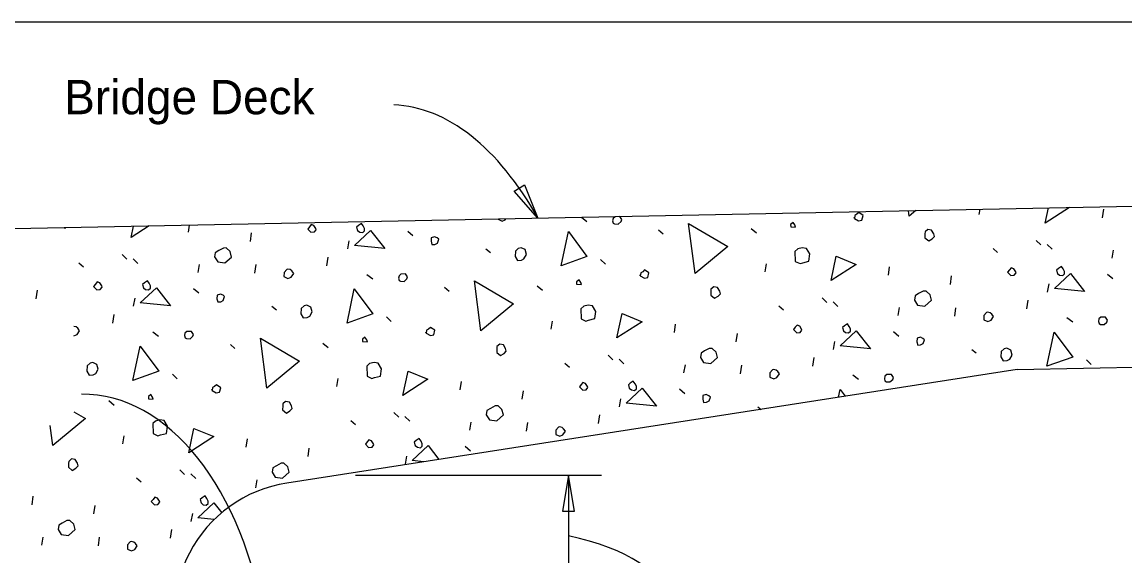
# Model space of a CAD drawing. Extents: x 112544 to 112597.1, y 111084 to 111107.1.
# Drawn here: x 112547.426 to 112552.277, y 111103.015 to 111105.363 of the extents above; entities that cross this region are included whole.
import ezdxf

# ---------------------------------------------------------------- set-up
doc = ezdxf.new("R2010")
doc.units = 0
for name, color, linetype in [('ActivePts-ConstElements', 7, 'Continuous'), ('Dimension', 7, 'Continuous'), ('Miscellaneous', 7, 'Continuous'), ('SupstrConc', 7, 'Continuous'), ('TextStructures', 7, 'Continuous')]:
    doc.layers.add(name, color=color, linetype=linetype)

msp = doc.modelspace()

# ---------------------------------------------------------------- linework, layer by layer
at = {"layer": 'ActivePts-ConstElements'}
msp.add_lwpolyline([(112543.9918, 111085.9039), (112574.7797, 111085.9039), (112574.7797, 111105.3634), (112543.9918, 111105.3634)], close=True, dxfattribs=at)
at = {"layer": 'Dimension'}
for p, q in [((112549.9754, 111103.3685), (112548.8921, 111103.3685)), ((112549.8296, 111103.3685), (112549.8296, 111102.8366))]:
    msp.add_line(p, q, dxfattribs=at)
for points in [[(112549.6951, 111104.5007), (112549.5904, 111104.6196), (112549.6355, 111104.6474)], [(112549.8296, 111103.3684), (112549.8031, 111103.2122), (112549.856, 111103.2122)]]:
    msp.add_lwpolyline(points, close=True, dxfattribs=at)
for centre, major_axis, ratio, start_param, end_param in [((112548.95, 111102.6319), (-0.1111, -2.3674), 0.464296, 2.502126, 3.141581), ((112547.7047, 111102.4058), (0.0174, -1.3204), 0.616683, 1.795781, 3.141615), ((112549.4704, 111102.8192), (-0.7827, 0), 0.407451, 3.141527, 4.235533)]:
    msp.add_ellipse(centre, major_axis=major_axis, ratio=ratio, start_param=start_param, end_param=end_param, dxfattribs=at)
at = {"layer": 'Miscellaneous'}
for p, q in [((112551.6363, 111104.5169), (112551.6402, 111104.5397)), ((112552.1787, 111104.5018), (112552.1841, 111104.5395)), ((112549.886, 111104.5046), (112549.9103, 111104.4867)), ((112547.6155, 111104.4542), (112547.6164, 111104.4592)), ((112548.1579, 111104.439), (112548.1624, 111104.4701)), ((112548.4303, 111104.3981), (112548.4357, 111104.4358)), ((112549.1221, 111104.4437), (112549.1454, 111104.4241)), ((112550.2257, 111104.4496), (112550.246, 111104.4317)), ((112550.6331, 111104.4552), (112550.6564, 111104.4356)), ((112548.8584, 111104.3653), (112548.8644, 111104.4006)), ((112551.8868, 111104.4029), (112551.9078, 111104.3826)), ((112551.9356, 111104.3849), (112551.9566, 111104.3647)), ((112547.8661, 111104.3401), (112547.887, 111104.3199)), ((112549.4666, 111104.3652), (112549.4863, 111104.3498)), ((112551.697, 111104.3676), (112551.7173, 111104.3497)), ((112552.2211, 111104.3242), (112552.2272, 111104.3595)), ((112547.6762, 111104.3048), (112547.6966, 111104.2869)), ((112547.9149, 111104.3221), (112547.9358, 111104.3019)), ((112548.2003, 111104.2615), (112548.2064, 111104.2967)), ((112548.4496, 111104.2584), (112548.455, 111104.2961)), ((112548.7668, 111104.2916), (112548.7723, 111104.3293)), ((112549.9707, 111104.3191), (112549.9917, 111104.2989)), ((112550.6945, 111104.2646), (112550.7006, 111104.2999)), ((112551.2369, 111104.2495), (112551.2423, 111104.2872)), ((112548.9427, 111104.2533), (112548.9685, 111104.2343)), ((112551.5093, 111104.2086), (112551.5147, 111104.2463)), ((112552.201, 111104.2542), (112552.2244, 111104.2345)), ((112548.1803, 111104.1914), (112548.2037, 111104.1718)), ((112549.2839, 111104.1972), (112549.3042, 111104.1794)), ((112549.6913, 111104.2028), (112549.7147, 111104.1832)), ((112551.9373, 111104.1757), (112551.9434, 111104.211)), ((112547.4885, 111104.1458), (112547.4939, 111104.1835)), ((112547.9166, 111104.113), (112547.9227, 111104.1482)), ((112550.945, 111104.1506), (112550.966, 111104.1303)), ((112548.5248, 111104.1129), (112548.5445, 111104.0974)), ((112550.7552, 111104.1152), (112550.7755, 111104.0974)), ((112550.9939, 111104.1326), (112551.0148, 111104.1123)), ((112551.2793, 111104.0719), (112551.2854, 111104.1072)), ((112551.5286, 111104.0688), (112551.534, 111104.1065)), ((112551.8458, 111104.102), (112551.8512, 111104.1397)), ((112547.825, 111104.0393), (112547.8305, 111104.0769)), ((112549.0289, 111104.0668), (112549.0499, 111104.0465)), ((112549.7527, 111104.0122), (112549.7588, 111104.0475)), ((112552.0217, 111104.0638), (112552.0475, 111104.0448)), ((112548.0009, 111104.001), (112548.0267, 111103.982)), ((112550.2951, 111103.9971), (112550.3005, 111104.0348)), ((112551.2593, 111104.0018), (112551.2826, 111103.9822)), ((112548.7495, 111103.9505), (112548.7729, 111103.9309)), ((112550.5675, 111103.9562), (112550.5729, 111103.9939)), ((112550.9956, 111103.9234), (112551.0016, 111103.9587)), ((112548.3421, 111103.9449), (112548.3624, 111103.927)), ((112550.0033, 111103.8982), (112550.0242, 111103.8779)), ((112551.6038, 111103.9233), (112551.6235, 111103.9079)), ((112549.8134, 111103.8629), (112549.8338, 111103.845)), ((112550.0521, 111103.8802), (112550.073, 111103.86)), ((112550.3375, 111103.8195), (112550.3436, 111103.8548)), ((112550.5868, 111103.8165), (112550.5922, 111103.8541)), ((112550.904, 111103.8497), (112550.9095, 111103.8874)), ((112552.1079, 111103.8772), (112552.1289, 111103.857)), ((112548.0872, 111103.8144), (112548.1081, 111103.7942)), ((112551.0799, 111103.8114), (112551.1057, 111103.7924)), ((112548.8109, 111103.7599), (112548.817, 111103.7952)), ((112549.3533, 111103.7448), (112549.3588, 111103.7825)), ((112549.6257, 111103.7039), (112549.6311, 111103.7416)), ((112550.0538, 111103.671), (112550.0599, 111103.7063)), ((112550.3175, 111103.7495), (112550.3408, 111103.7298)), ((112547.8077, 111103.6981), (112547.8311, 111103.6785)), ((112550.662, 111103.671), (112550.6766, 111103.6595)), ((112548.8717, 111103.6105), (112548.892, 111103.5927)), ((112549.0615, 111103.6459), (112549.0825, 111103.6256)), ((112549.1103, 111103.6279), (112549.1313, 111103.6076)), ((112549.9622, 111103.5973), (112549.9677, 111103.635)), ((112549.3957, 111103.5672), (112549.4018, 111103.6025)), ((112549.645, 111103.5641), (112549.6505, 111103.6018)), ((112547.8692, 111103.5076), (112547.8752, 111103.5428)), ((112548.4116, 111103.4924), (112548.417, 111103.5301)), ((112548.6839, 111103.4515), (112548.6894, 111103.4892)), ((112549.3757, 111103.4971), (112549.3991, 111103.4775)), ((112549.112, 111103.4187), (112549.1181, 111103.454)), ((112548.1197, 111103.3935), (112548.1407, 111103.3732)), ((112548.1685, 111103.3755), (112548.1895, 111103.3553)), ((112547.9299, 111103.3582), (112547.9502, 111103.3403)), ((112548.454, 111103.3148), (112548.46, 111103.3501)), ((112547.4698, 111103.2401), (112547.4752, 111103.2778)), ((112547.7421, 111103.1992), (112547.7476, 111103.2369)), ((112548.1702, 111103.1663), (112548.1763, 111103.2016)), ((112548.0787, 111103.0926), (112548.0841, 111103.1303)), ((112547.5122, 111103.0625), (112547.5183, 111103.0978)), ((112547.7615, 111103.0594), (112547.7669, 111103.0971))]:
    msp.add_line(p, q, dxfattribs=at)
for points in [[(112551.3277, 111104.5093), (112551.3247, 111104.5334)], [(112551.3577, 111104.534), (112551.3277, 111104.5093)], [(112552.0341, 111104.5476), (112551.9262, 111104.4782)], [(112551.9262, 111104.4782), (112551.9407, 111104.5457)], [(112549.5196, 111104.4973), (112549.5196, 111104.4959), (112549.5373, 111104.4877), (112549.5512, 111104.494), (112549.554, 111104.498)], [(112550.0262, 111104.4789), (112550.0324, 111104.4754), (112550.0482, 111104.4745), (112550.0607, 111104.4856), (112550.0636, 111104.4941), (112550.0549, 111104.5073), (112550.0343, 111104.507), (112550.0259, 111104.4996), (112550.0237, 111104.4886), (112550.0262, 111104.4789)], [(112550.807, 111104.463), (112550.8282, 111104.4609), (112550.8257, 111104.4706), (112550.8176, 111104.4813), (112550.8068, 111104.4733), (112550.807, 111104.463)], [(112551.0872, 111104.4992), (112551.1055, 111104.4886), (112551.12, 111104.4925), (112551.1251, 111104.512), (112551.1061, 111104.525), (112551.0978, 111104.5176), (112551.0887, 111104.5126), (112551.0872, 111104.4992), (112551.0859, 111104.504)], [(112547.985, 111104.4666), (112547.9054, 111104.4154)], [(112547.9054, 111104.4154), (112547.9162, 111104.4652)], [(112548.6822, 111104.4527), (112548.6964, 111104.4384), (112548.7116, 111104.4399), (112548.7193, 111104.4497), (112548.718, 111104.4545), (112548.7093, 111104.4677), (112548.6977, 111104.4724), (112548.69, 111104.4625), (112548.6822, 111104.4527)], [(112548.8878, 111104.381), (112548.9583, 111104.4464), (112549.0209, 111104.3674), (112548.8878, 111104.381)], [(112548.9013, 111104.4467), (112548.9111, 111104.439), (112548.9245, 111104.4374), (112548.9328, 111104.4448), (112548.9327, 111104.4551), (112548.927, 111104.4665), (112548.9189, 111104.4773), (112548.9057, 111104.4686), (112548.8974, 111104.4612), (112548.9013, 111104.4467)], [(112549.7972, 111104.2907), (112549.8292, 111104.4417), (112549.9105, 111104.3315), (112549.7972, 111104.2907)], [(112550.386, 111104.257), (112550.358, 111104.4772), (112550.5301, 111104.3758), (112550.386, 111104.257)], [(112551.3976, 111104.4323), (112551.3973, 111104.4141), (112551.4139, 111104.4004), (112551.4295, 111104.4098), (112551.4396, 111104.4202), (112551.4364, 111104.4323), (112551.427, 111104.4479), (112551.4106, 111104.4513), (112551.398, 111104.4402), (112551.3976, 111104.4323)], [(112549.2247, 111104.3988), (112549.2286, 111104.3843), (112549.2413, 111104.3851), (112549.2527, 111104.3907), (112549.2585, 111104.4078), (112549.2517, 111104.4138), (112549.2401, 111104.4184), (112549.2256, 111104.4145), (112549.2247, 111104.3988)], [(112548.2725, 111104.33), (112548.2863, 111104.3078), (112548.3185, 111104.3035), (112548.3478, 111104.3294), (112548.3413, 111104.3536), (112548.324, 111104.3697), (112548.3113, 111104.3688), (112548.2909, 111104.3582), (112548.2753, 111104.3488), (112548.2725, 111104.33)], [(112549.5959, 111104.3559), (112549.5945, 111104.3322), (112549.6045, 111104.3142), (112549.6221, 111104.3163), (112549.6335, 111104.3219), (112549.6441, 111104.3403), (112549.6383, 111104.3621), (112549.6206, 111104.3702), (112549.6085, 111104.367), (112549.5959, 111104.3559)], [(112550.8258, 111104.3541), (112550.8271, 111104.3105), (112550.8479, 111104.3005), (112550.86, 111104.3038), (112550.8866, 111104.3109), (112550.8909, 111104.3431), (112550.8765, 111104.3677), (112550.8577, 111104.3704), (112550.8383, 111104.3653), (112550.8258, 111104.3541)], [(112550.9844, 111104.2258), (112551.0075, 111104.3329), (112551.0948, 111104.2968), (112550.9844, 111104.2258)], [(112551.9802, 111104.2571), (112551.9901, 111104.2494), (112552.0034, 111104.2478), (112552.0118, 111104.2552), (112552.0116, 111104.2655), (112552.006, 111104.277), (112551.9979, 111104.2877), (112551.9847, 111104.279), (112551.9764, 111104.2716), (112551.9802, 111104.2571)], [(112548.5781, 111104.2617), (112548.5778, 111104.2435), (112548.5955, 111104.2354), (112548.6094, 111104.2416), (112548.6206, 111104.2576), (112548.6126, 111104.2684), (112548.6058, 111104.2743), (112548.5949, 111104.2766), (112548.59, 111104.2753), (112548.5781, 111104.2617)], [(112549.0845, 111104.2266), (112549.0906, 111104.2231), (112549.1064, 111104.2221), (112549.1189, 111104.2332), (112549.1218, 111104.2418), (112549.1131, 111104.255), (112549.0925, 111104.2546), (112549.0841, 111104.2472), (112549.0819, 111104.2363), (112549.0845, 111104.2266)], [(112550.1454, 111104.2469), (112550.1637, 111104.2363), (112550.1782, 111104.2401), (112550.1834, 111104.2596), (112550.1643, 111104.2727), (112550.156, 111104.2652), (112550.147, 111104.2602), (112550.1454, 111104.2469), (112550.1441, 111104.2517)], [(112551.7612, 111104.2631), (112551.7754, 111104.2488), (112551.7905, 111104.2503), (112551.7983, 111104.2601), (112551.797, 111104.265), (112551.7883, 111104.2781), (112551.7767, 111104.2828), (112551.7689, 111104.273), (112551.7612, 111104.2631)], [(112551.9668, 111104.1914), (112552.0373, 111104.2569), (112552.0998, 111104.1779), (112551.9668, 111104.1914)], [(112547.7405, 111104.2003), (112547.7547, 111104.186), (112547.7698, 111104.1875), (112547.7775, 111104.1973), (112547.7762, 111104.2022), (112547.7675, 111104.2154), (112547.7559, 111104.22), (112547.7482, 111104.2102), (112547.7405, 111104.2003)], [(112547.946, 111104.1286), (112548.0165, 111104.1941), (112548.0791, 111104.1151), (112547.946, 111104.1286)], [(112547.9595, 111104.1943), (112547.9693, 111104.1866), (112547.9827, 111104.185), (112547.9911, 111104.1924), (112547.9909, 111104.2027), (112547.9852, 111104.2142), (112547.9772, 111104.225), (112547.964, 111104.2162), (112547.9556, 111104.2088), (112547.9595, 111104.1943)], [(112548.8554, 111104.0384), (112548.8874, 111104.1893), (112548.9687, 111104.0791), (112548.8554, 111104.0384)], [(112549.4442, 111104.0046), (112549.4162, 111104.2249), (112549.5883, 111104.1235), (112549.4442, 111104.0046)], [(112549.8652, 111104.2106), (112549.8865, 111104.2086), (112549.8839, 111104.2182), (112549.8758, 111104.229), (112549.865, 111104.2209), (112549.8652, 111104.2106)], [(112550.4558, 111104.1799), (112550.4555, 111104.1617), (112550.4721, 111104.1481), (112550.4877, 111104.1574), (112550.4978, 111104.1679), (112550.4946, 111104.18), (112550.4852, 111104.1956), (112550.4688, 111104.1989), (112550.4562, 111104.1878), (112550.4558, 111104.1799)], [(112548.2829, 111104.1464), (112548.2868, 111104.1319), (112548.2995, 111104.1327), (112548.3109, 111104.1384), (112548.3167, 111104.1555), (112548.3099, 111104.1614), (112548.2983, 111104.1661), (112548.2839, 111104.1622), (112548.2829, 111104.1464)], [(112551.3515, 111104.1404), (112551.3652, 111104.1182), (112551.3975, 111104.1139), (112551.4267, 111104.1399), (112551.4203, 111104.164), (112551.403, 111104.1801), (112551.3903, 111104.1793), (112551.3698, 111104.1686), (112551.3542, 111104.1593), (112551.3515, 111104.1404)], [(112548.6542, 111104.1035), (112548.6527, 111104.0799), (112548.6627, 111104.0618), (112548.6803, 111104.0639), (112548.6917, 111104.0696), (112548.7023, 111104.088), (112548.6965, 111104.1097), (112548.6788, 111104.1179), (112548.6667, 111104.1147), (112548.6542, 111104.1035)], [(112549.884, 111104.1018), (112549.8854, 111104.0581), (112549.9061, 111104.0482), (112549.9182, 111104.0514), (112549.9448, 111104.0585), (112549.9491, 111104.0907), (112549.9347, 111104.1154), (112549.9159, 111104.1181), (112549.8966, 111104.1129), (112549.884, 111104.1018)], [(112550.0426, 111103.9735), (112550.0657, 111104.0806), (112550.153, 111104.0445), (112550.0426, 111103.9735)], [(112551.6571, 111104.0722), (112551.6568, 111104.054), (112551.6745, 111104.0458), (112551.6884, 111104.0521), (112551.6996, 111104.068), (112551.6916, 111104.0788), (112551.6848, 111104.0848), (112551.6738, 111104.087), (112551.669, 111104.0857), (112551.6571, 111104.0722)], [(112552.1634, 111104.037), (112552.1696, 111104.0335), (112552.1854, 111104.0326), (112552.1979, 111104.0437), (112552.2008, 111104.0522), (112552.1921, 111104.0654), (112552.1715, 111104.0651), (112552.1631, 111104.0576), (112552.1609, 111104.0467), (112552.1634, 111104.037)], [(112547.6542, 111103.9832), (112547.6676, 111103.9893), (112547.6789, 111104.0053), (112547.6708, 111104.016), (112547.664, 111104.022), (112547.6542, 111104.024)], [(112548.1427, 111103.9742), (112548.1488, 111103.9707), (112548.1646, 111103.9698), (112548.1771, 111103.9809), (112548.18, 111103.9894), (112548.1713, 111104.0026), (112548.1507, 111104.0023), (112548.1423, 111103.9949), (112548.1401, 111103.9839), (112548.1427, 111103.9742)], [(112549.2036, 111103.9945), (112549.222, 111103.9839), (112549.2365, 111103.9878), (112549.2416, 111104.0073), (112549.2226, 111104.0203), (112549.2142, 111104.0129), (112549.2052, 111104.0079), (112549.2036, 111103.9945), (112549.2023, 111103.9994)], [(112550.8194, 111104.0108), (112550.8336, 111103.9965), (112550.8488, 111103.9979), (112550.8565, 111104.0078), (112550.8552, 111104.0126), (112550.8465, 111104.0258), (112550.8349, 111104.0305), (112550.8272, 111104.0206), (112550.8194, 111104.0108)], [(112551.025, 111103.939), (112551.0955, 111104.0045), (112551.1581, 111103.9255), (112551.025, 111103.939)], [(112551.0385, 111104.0048), (112551.0483, 111103.9971), (112551.0617, 111103.9955), (112551.07, 111104.0029), (112551.0699, 111104.0132), (112551.0642, 111104.0246), (112551.0561, 111104.0354), (112551.0429, 111104.0267), (112551.0346, 111104.0193), (112551.0385, 111104.0048)], [(112551.9344, 111103.8488), (112551.9664, 111103.9998), (112552.0477, 111103.8895), (112551.9344, 111103.8488)], [(112548.5024, 111103.7523), (112548.4744, 111103.9726), (112548.6465, 111103.8711), (112548.5024, 111103.7523)], [(112548.9234, 111103.9583), (112548.9447, 111103.9562), (112548.9421, 111103.9659), (112548.934, 111103.9766), (112548.9233, 111103.9686), (112548.9234, 111103.9583)], [(112549.514, 111103.9276), (112549.5137, 111103.9094), (112549.5303, 111103.8957), (112549.5459, 111103.9051), (112549.556, 111103.9156), (112549.5528, 111103.9276), (112549.5434, 111103.9432), (112549.527, 111103.9466), (112549.5145, 111103.9355), (112549.514, 111103.9276)], [(112551.3619, 111103.9568), (112551.3658, 111103.9424), (112551.3785, 111103.9432), (112551.3899, 111103.9488), (112551.3957, 111103.9659), (112551.3889, 111103.9719), (112551.3773, 111103.9765), (112551.3628, 111103.9726), (112551.3619, 111103.9568)], [(112547.9136, 111103.786), (112547.9456, 111103.937), (112548.0269, 111103.8268), (112547.9136, 111103.786)], [(112550.4097, 111103.8881), (112550.4235, 111103.8659), (112550.4557, 111103.8616), (112550.485, 111103.8875), (112550.4785, 111103.9117), (112550.4612, 111103.9277), (112550.4485, 111103.9269), (112550.4281, 111103.9163), (112550.4125, 111103.9069), (112550.4097, 111103.8881)], [(112551.7331, 111103.914), (112551.7317, 111103.8903), (112551.7417, 111103.8723), (112551.7593, 111103.8744), (112551.7707, 111103.88), (112551.7813, 111103.8984), (112551.7755, 111103.9201), (112551.7578, 111103.9283), (112551.7457, 111103.9251), (112551.7331, 111103.914)], [(112547.7124, 111103.8512), (112547.711, 111103.8275), (112547.721, 111103.8095), (112547.7385, 111103.8116), (112547.7499, 111103.8172), (112547.7606, 111103.8356), (112547.7547, 111103.8574), (112547.737, 111103.8655), (112547.7249, 111103.8623), (112547.7124, 111103.8512)], [(112548.9422, 111103.8494), (112548.9436, 111103.8058), (112548.9644, 111103.7958), (112548.9764, 111103.7991), (112549.003, 111103.8062), (112549.0073, 111103.8384), (112548.993, 111103.863), (112548.9741, 111103.8657), (112548.9548, 111103.8606), (112548.9422, 111103.8494)], [(112549.1009, 111103.7211), (112549.1239, 111103.8282), (112549.2112, 111103.7921), (112549.1009, 111103.7211)], [(112550.7153, 111103.8198), (112550.715, 111103.8016), (112550.7327, 111103.7934), (112550.7466, 111103.7997), (112550.7578, 111103.8157), (112550.7498, 111103.8265), (112550.743, 111103.8324), (112550.732, 111103.8347), (112550.7272, 111103.8334), (112550.7153, 111103.8198)], [(112551.2217, 111103.7847), (112551.2278, 111103.7812), (112551.2436, 111103.7802), (112551.2561, 111103.7913), (112551.259, 111103.7999), (112551.2503, 111103.8131), (112551.2297, 111103.8127), (112551.2213, 111103.8053), (112551.2191, 111103.7943), (112551.2217, 111103.7847)], [(112548.2618, 111103.7422), (112548.2802, 111103.7316), (112548.2947, 111103.7354), (112548.2998, 111103.7549), (112548.2808, 111103.768), (112548.2724, 111103.7605), (112548.2634, 111103.7555), (112548.2618, 111103.7422), (112548.2605, 111103.747)], [(112549.8777, 111103.7584), (112549.8919, 111103.7441), (112549.907, 111103.7456), (112549.9147, 111103.7554), (112549.9134, 111103.7603), (112549.9047, 111103.7734), (112549.8931, 111103.7781), (112549.8854, 111103.7683), (112549.8777, 111103.7584)], [(112550.0832, 111103.6867), (112550.1537, 111103.7522), (112550.2163, 111103.6732), (112550.0832, 111103.6867)], [(112550.0967, 111103.7524), (112550.1065, 111103.7447), (112550.1199, 111103.7431), (112550.1283, 111103.7505), (112550.1281, 111103.7608), (112550.1224, 111103.7723), (112550.1144, 111103.783), (112550.1012, 111103.7743), (112550.0928, 111103.7669), (112550.0967, 111103.7524)], [(112547.9817, 111103.7059), (112548.0029, 111103.7039), (112548.0003, 111103.7135), (112547.9923, 111103.7243), (112547.9815, 111103.7162), (112547.9817, 111103.7059)], [(112550.4201, 111103.7045), (112550.424, 111103.69), (112550.4367, 111103.6908), (112550.4481, 111103.6965), (112550.4539, 111103.7136), (112550.4471, 111103.7195), (112550.4355, 111103.7242), (112550.4211, 111103.7203), (112550.4201, 111103.7045)], [(112551.0172, 111103.7124), (112551.0246, 111103.7474), (112551.047, 111103.7171)], [(112548.5722, 111103.6752), (112548.5719, 111103.657), (112548.5885, 111103.6434), (112548.6041, 111103.6527), (112548.6143, 111103.6632), (112548.611, 111103.6753), (112548.6017, 111103.6909), (112548.5852, 111103.6942), (112548.5727, 111103.6831), (112548.5722, 111103.6752)], [(112549.468, 111103.6357), (112549.4817, 111103.6135), (112549.5139, 111103.6092), (112549.5432, 111103.6352), (112549.5367, 111103.6593), (112549.5195, 111103.6754), (112549.5067, 111103.6746), (112549.4863, 111103.6639), (112549.4707, 111103.6546), (112549.468, 111103.6357)], [(112547.6542, 111103.6486), (112547.7048, 111103.6188), (112547.5606, 111103.4999)], [(112548.0005, 111103.5971), (112548.0018, 111103.5534), (112548.0226, 111103.5435), (112548.0347, 111103.5467), (112548.0612, 111103.5538), (112548.0655, 111103.5861), (112548.0512, 111103.6107), (112548.0323, 111103.6134), (112548.013, 111103.6082), (112548.0005, 111103.5971)], [(112547.5606, 111103.4999), (112547.5494, 111103.5883)], [(112548.1591, 111103.4688), (112548.1821, 111103.5759), (112548.2695, 111103.5398), (112548.1591, 111103.4688)], [(112549.7735, 111103.5675), (112549.7732, 111103.5493), (112549.791, 111103.5411), (112549.8048, 111103.5474), (112549.8161, 111103.5633), (112549.808, 111103.5741), (112549.8012, 111103.5801), (112549.7903, 111103.5823), (112549.7854, 111103.581), (112549.7735, 111103.5675)], [(112548.9359, 111103.5061), (112548.9501, 111103.4918), (112548.9652, 111103.4932), (112548.9729, 111103.5031), (112548.9716, 111103.5079), (112548.9629, 111103.5211), (112548.9513, 111103.5258), (112548.9436, 111103.5159), (112548.9359, 111103.5061)], [(112549.1549, 111103.5001), (112549.1647, 111103.4924), (112549.1781, 111103.4908), (112549.1865, 111103.4982), (112549.1863, 111103.5085), (112549.1807, 111103.5199), (112549.1726, 111103.5307), (112549.1594, 111103.522), (112549.151, 111103.5146), (112549.1549, 111103.5001)], [(112549.1415, 111103.4344), (112549.2119, 111103.4998), (112549.2598, 111103.4394)], [(112547.6304, 111103.4229), (112547.6301, 111103.4047), (112547.6467, 111103.391), (112547.6624, 111103.4004), (112547.6725, 111103.4109), (112547.6693, 111103.4229), (112547.6599, 111103.4385), (112547.6435, 111103.4419), (112547.6309, 111103.4308), (112547.6304, 111103.4229)], [(112548.5262, 111103.3834), (112548.5399, 111103.3612), (112548.5721, 111103.3569), (112548.6014, 111103.3828), (112548.5949, 111103.407), (112548.5777, 111103.423), (112548.565, 111103.4222), (112548.5445, 111103.4116), (112548.5289, 111103.4022), (112548.5262, 111103.3834)], [(112549.1936, 111103.4291), (112549.1415, 111103.4344)], [(112547.9941, 111103.2537), (112548.0083, 111103.2394), (112548.0234, 111103.2409), (112548.0312, 111103.2507), (112548.0299, 111103.2556), (112548.0211, 111103.2688), (112548.0095, 111103.2734), (112548.0018, 111103.2636), (112547.9941, 111103.2537)], [(112548.2131, 111103.2477), (112548.223, 111103.24), (112548.2363, 111103.2384), (112548.2447, 111103.2458), (112548.2445, 111103.2561), (112548.2389, 111103.2676), (112548.2308, 111103.2783), (112548.2176, 111103.2696), (112548.2092, 111103.2622), (112548.2131, 111103.2477)], [(112548.1997, 111103.182), (112548.2701, 111103.2475), (112548.3039, 111103.2048)], [(112547.5844, 111103.131), (112547.5981, 111103.1088), (112547.6303, 111103.1045), (112547.6596, 111103.1305), (112547.6531, 111103.1546), (112547.6359, 111103.1707), (112547.6232, 111103.1699), (112547.6027, 111103.1592), (112547.5871, 111103.1499), (112547.5844, 111103.131)], [(112548.2709, 111103.1748), (112548.1997, 111103.182)], [(112547.89, 111103.0628), (112547.8897, 111103.0446), (112547.9074, 111103.0364), (112547.9213, 111103.0427), (112547.9325, 111103.0587), (112547.9244, 111103.0694), (112547.9177, 111103.0754), (112547.9067, 111103.0776), (112547.9019, 111103.0763), (112547.89, 111103.0628)]]:
    msp.add_lwpolyline(points, dxfattribs=at)
at = {"layer": 'SupstrConc'}
for p, q in [((112544.6086, 111104.3991), (112554.7971, 111104.6028)), ((112551.8027, 111103.8345), (112554.7971, 111103.8944)), ((112551.8027, 111103.8345), (112548.5904, 111103.3353))]:
    msp.add_line(p, q, dxfattribs=at)
msp.add_arc((112548.68, 111102.759), 0.5833, 98.8325, 206.4422, dxfattribs=at)

# ---------------------------------------------------------------- texts
at = {"layer": 'TextStructures'}
msp.add_text('Bridge Deck', height=0.1512, dxfattribs=at).set_placement((112547.6113, 111104.9578))

doc.saveas('drawing.dxf')
